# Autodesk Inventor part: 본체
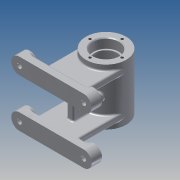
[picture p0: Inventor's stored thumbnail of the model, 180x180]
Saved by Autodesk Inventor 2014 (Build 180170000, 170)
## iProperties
Created: 2015-11
Part Number: 본체
Material: 알루미늄 6061
Document SubType Name: Modeling
Designer: 12
Density: 2.71 g/cm^3
Appearance: 알루미늄 - 평지
Mass: 358.859 g
Surface Area: 459.451 cm^2
Volume: 132.42 cm^3
Author: 12
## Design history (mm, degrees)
sketch "스케치2"
  geometry: C1 r 25 at (0, 0); 1 further point
  constraints: 1 centre point, 1 coincident
  dimensions: "d0" = 50 diameter of C1
extrude "돌출1" new body sketch "스케치2" stored distance "d1" = 70; taper "d2" = 0 deg
node "작업 평면1"
sketch "스케치5"
  geometry: L1 (-50, 30)-(50, 30); L2 (-40, 20)-(40, 20); L3 (40, 40)-(-40, 40); L4 (-82.769, 0)-(87.692, 0); L5 (40, -40)-(-40, -40); L6 (-40, -20)-(40, -20); A1 r 10 centre (-40, 30) between (-40, 40) and (-40, 20); A2 r 10 centre (40, 30) between (40, 20) and (40, 40); A3 r 10 centre (-40, -30) between (-40, -20) and (-40, -40); A4 r 10 centre (40, -30) between (40, -40) and (40, -20); 2 further points
  constraints: 14 end point, 10 point on circle, 6 symmetric about line, 4 centre point, 4 tangent, 3 point on line, 2 parallel, 1 horizontal, 1 midpoint, 1 vertical alignment, 2 other
  dimensions: "d15" = 80 distance of A2.centre A1.centre; "d16" = 40 distance from line of point (0, 0) L3; "d17" = 10 radius of A1
extrude "돌출3" join sketch "스케치5" distance "d18" = 10; taper "d19" = 0 deg
sketch "스케치6"
  geometry: L1 (25, -35)-(-25, -35) reference; L2 (-25, -35)-(-25, 35) reference; L3 (-25, 35)-(25, 35) reference; L4 (25, 35)-(25, -35) reference; L5 (-58, -40)-(-68, -40) reference; L6 (-68, -40)-(-68, -20) reference; L7 (-68, -20)-(-58, -20) reference; L8 (-58, -20)-(-58, -40) reference; L9 (-58, 20)-(-68, 20) reference; L10 (-68, 20)-(-68, 40) reference; L11 (-68, 40)-(-58, 40) reference; L12 (-58, 40)-(-58, 20) reference; L13 (-58, 20)-(0, 20); L14 (0, 20)-(0, 28); L15 (0, 28)-(-58, 28); L16 (-58, -20)-(0, -20); L17 (0, -20)-(0, -28); L18 (0, -28)-(-58, -28); 1 further point
  constraints: 12 end point, 4 perpendicular, 2 parallel, 2 point on line
  dimensions: "d20" = 8 distance of L13.end L14.end; "d21" = 58 distance of L15.end L14.end; "d22" = 8 distance of L16.end L17.end; "d23" = 58 distance of L7.end L16.end
extrude "돌출4" join sketch "스케치6" stored distance "d24" = 50; taper "d25" = 0 deg
sketch "스케치8"
  geometry: L1 (0, 20)-(-58, 20) reference; L2 (-58, -20)-(0, -20) reference; L3 (-45, 20)-(-45, -20); L4 (-4.716, 20)-(-4.716, -20); L5 (25, 35)-(-25, 35) reference; 1 further point
  constraints: 4 end point, 4 point on line, 2 perpendicular
  dimensions: "d30" = 4.71573 distance from line of L1.start L4; "d33" = 20 horizontal distance of L3.start L5.end
extrude "돌출5" join sketch "스케치8" stored distance "d31" = 8; taper "d32" = 0 deg
sketch "스케치9"
  geometry: L1 (-35, 11.5)-(-35, -11.5); L2 (-38.5, 8)-(-38.5, -8); L3 (-31.5, -8)-(-31.5, 8); L4 (-68, -20)-(-68, -40) reference; A1 r 3.5 centre (-35, 8) between (-31.5, 8) and (-38.5, 8); A2 r 3.5 centre (-35, -8) between (-38.5, -8) and (-31.5, -8); 2 further points
  constraints: 8 end point, 6 point on circle, 4 tangent, 2 centre point, 2 point on line, 1 midpoint, 1 parallel, 1 vertical
  dimensions: "d34" = 33 distance from line of L4 A2.centre; "d35" = 3.5 radius of A2; "d36" = 23 distance of L1.start L1.end; "d38" = 0 vertical distance of point (-35, 0) point (0, 0)
extrude "돌출6" cut sketch "스케치9" stored distance "d39" = 8; taper "d40" = 0 deg
node "작업 평면3"
sketch "스케치10"
  geometry: C1 r 5 at (0, 0); 1 further point
  constraints: 1 centre point, 1 coincident
  dimensions: "d41" = 10 diameter of C1
extrude "돌출7" join sketch "스케치10" distance "d42" = 3; taper "d44" = 0 deg; dims "d43" = 10, "d45" = 0
sketch "스케치13"
  geometry: L1 (-40, 40)-(40, 40) reference; L2 (40, 20)-(-40, 20) reference; C1 r 10 at (-40, -30); C2 r 10 at (40, -30); C3 r 10 at (40, 30); A1 r 10 centre (-40, -30) between (-40, -20) and (-40, -40) reference; A2 r 10 centre (40, -30) between (40, -40) and (40, -20) reference; A3 r 10 centre (40, 30) between (40, 20) and (40, 40) reference; A4 r 10 centre (-40, 30) between (-40, 40) and (-40, 20) reference; 2 further points
  constraints: 4 coincident, 3 centre point, 3 concentric, 1 vertical alignment, 2 other
extrude "돌출9" join sketch "스케치13" distance "d56" = 3; taper "d57" = 0 deg
node "작업 평면5"
sketch "스케치14"
  geometry: L1 (25, 20)-(-25, 20) reference; L2 (-25, 20)-(-25, 28) reference; L3 (-25, 28)-(25, 28) reference; L4 (25, 28)-(25, 20) reference; L5 (25, -28)-(-25, -28) reference; L6 (-25, -28)-(-25, -20) reference; L7 (-25, -20)-(25, -20) reference; L8 (25, -20)-(25, -28) reference; C1 r 10 at (40, -30) reference; C2 r 10 at (-40, -30) reference; C3 r 10 at (40, 30) reference; C4 r 10 at (-40, 30) reference; 5 further points
  constraints: 4 coincident
hole "구멍1" sketch "스케치14" at (-40, 30), (-40, -30), (40, -30), (40, 30) diameter "d59" = 6; stored, may be unused: countersink angle "d63" = 90 deg, drill point angle "d65" = 0 deg; dims "d60" = 6, "d61" = 12, "d62" = 4, "d64" = 13
sketch "스케치15"
  geometry: L1 (0, 40.643)-(0, -41.854); L2 (-38.5, 8)-(-38.5, -8) reference; L3 (-31.5, -8)-(-31.5, 8) reference; L4 (-25, 28)-(-25, 35) reference; L5 (-25, 35)-(25, 35) reference; L6 (25, 35)-(25, 5) reference; L7 (25, 5)-(28, 5) reference; L8 (28, 5)-(28, -5) reference; L9 (28, -5)-(25, -5) reference; L10 (25, -5)-(25, -35) reference; L11 (25, -35)-(-25, -35) reference; L12 (-25, -35)-(-25, -28) reference; L13 (-25, -28)-(-58, -28) reference; L14 (-58, -28)-(-58, -40) reference; L15 (-58, -40)-(-68, -40) reference; L16 (-68, -40)-(-68, -20) reference; L17 (-68, -20)-(-45, -20) reference; L18 (-45, -20)-(-45, 20) reference; L19 (-45, 20)-(-68, 20) reference; L20 (-68, 20)-(-68, 40) reference; L21 (-68, 40)-(-58, 40) reference; L22 (-58, 40)-(-58, 28) reference; L23 (-58, 28)-(-25, 28) reference; L24 (0, 35)-(16, 35); L25 (16, 35)-(16, 23); L26 (16, 23)-(14, 23); L27 (14, 23)-(14, 21); L28 (14, 21)-(21, 21); L29 (21, 21)-(21, -21); L30 (21, -21)-(14, -21); L31 (14, -21)-(14, -23); L32 (14, -23)-(16, -23); L33 (16, -23)-(16, -35); L34 (16, -35)-(0, -35); L35 (0, 35)-(0, -35); A1 r 3.5 centre (-35, 8) between (-31.5, 8) and (-38.5, 8) reference; A2 r 3.5 centre (-35, -8) between (-38.5, -8) and (-31.5, -8) reference; 1 further point
  constraints: 26 end point, 6 parallel, 3 collinear, 3 perpendicular, 3 point on line, 2 midpoint, 1 vertical
  dimensions: "d66" = 32 diameter of L24.end L1; "d67" = 28 diameter of L26.end L1; "d68" = 12 distance of L24.end L25.end; "d69" = 42 diameter of L29 L1; "d70" = 42 distance of L28.end L29.end; "d72" = 32 diameter of L33 L1; "d73" = 2 distance of L30.end L31.end
revolve "회전1" sketch "스케치15" stored, may be unused: angle "d74" = 90 deg
sketch "스케치16"
  geometry: C1 r 16 at (0, 0) reference; 4 further points
  constraints: 1 vertical alignment, 5 other
  dimensions: "d75" = 20 distance of C1.centre point (0, 20); "d78" = 360 deg dimension on C1.centre point (0, 20) (derived)
hole "구멍2" sketch "스케치16" at (0, 20), (-20, 0), (0, -20), (20, 0) diameter "d80" = 3.242; stored, may be unused: countersink angle "d84" = 90 deg, drill point angle "d86" = 118 deg; dims "d81" = 8, "d82" = 12, "d83" = 4, "d85" = 10
sketch "스케치17"
  geometry: C1 r 5 at (0, 0) reference; 1 further point
  constraints: 1 coincident
hole "구멍3" sketch "스케치17" at (0, 0) diameter "d87" = 5.188; stored, may be unused: countersink angle "d91" = 90 deg, drill point angle "d93" = 0 deg; dims "d88" = 8, "d89" = 12, "d90" = 4, "d92" = 10
sketch "스케치18"
  geometry: C1 r 5 at (0, 0) reference; 1 further point
  constraints: 1 coincident
hole "구멍4" sketch "스케치18" at (0, 0) diameter "d94" = 5.188; stored, may be unused: countersink angle "d98" = 90 deg, drill point angle "d100" = 0 deg; dims "d95" = 8, "d96" = 12, "d97" = 4, "d99" = 10
chamfer "모따기1" distance "d101" = 1; stored, may be unused: second distance "d102" = 2, angle "d103" = 45 deg
fillet "모깎기1" dims "d104" = 0.3
fillet "모깎기2" dims "d105" = 3
fillet "모깎기3" dims "d106" = 2
fillet "모깎기4" dims "d107" = 2
fillet "모깎기5" dims "d108" = 2
fillet "모깎기6" dims "d109" = 2
fillet "모깎기7" dims "d110" = 2
fillet "모깎기8" dims "d111" = 2
fillet "모깎기9" dims "d112" = 2
fillet "모깎기10" dims "d113" = 2
node "작업 평면6"
sketch "스케치19"
  geometry: L1 (-25, -35)-(-25, 35) reference; L2 (-25, -35)-(25, -35) reference; 2 further points
  constraints: 1 other
  dimensions: "d115" = 25 distance from line of L1 point (0, 0); "d116" = 35 distance from line of point (0, 0) L2
feature "엠보싱1" sketch "스케치19" dims "d0" = 50, "d117" = 0.5, "d118" = 0
fillet "모깎기11" dims "d119" = 2
fillet "모깎기12" dims "d120" = 0.3
node "솔리드1"
pattern_circular "원형 패턴1" dims angle "d54" = 210 deg
mirror "대칭1"
node "투영된 루프1"
node "절단 모서리 투영1"
node "절단 모서리 투영3"
node "절단 모서리 투영4"
other parameters: "d3" = -68, "d58" = 3
